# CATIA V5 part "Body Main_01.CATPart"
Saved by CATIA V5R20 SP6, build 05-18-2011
Part number: Body Main_01
Bounding box of the stored display mesh (mm): x -1450 to 0, y -340 to 340, z 0 to 599.993
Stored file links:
  E:\#03 University\#02 영남 이공대\#01 2021\#02 여름 방학\#01 Documents\K-Move Page02 ASD01\Body Main_01.CATPart
  E:\#03 University\#02 영남 이공대\#01 2021\#02 여름 방학\#01 Documents\K-Move Page02 ASD01\Body Main_04.CATPart

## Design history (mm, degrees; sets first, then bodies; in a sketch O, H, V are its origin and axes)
Set1 "Reference Data"
  Point1 "Center Point": (0, 0, 0)
  Plane1 "Plane.1(X Dir=-1150mm)": type Offset, RefPlane yz-plane, Offset -1150
  Plane2 "Plane.2(Z Dir=540mm)": type Offset, RefPlane xy-plane, Offset 540
  Extract1: ExtractElem face of Pad1 from Sketch1.L1
  Boundary1: Boundary edge of Extract1
Body1 (main body)
  Body2
    Sketch1 on zx-plane, origin (0, 0, 0), H (-1, 0, 0), V (0, 0, 1)
      line L1 (0, 0) -> (0, 540)
      line L2 (0, 540) -> (1003.9895, 540)
      point P2 (1150, 540)
      arc A1 centre (814, 0) radius 636 from (1326.0055, 377.2881) to (1450, 0) cw
      point P4 (1450, 0)
      construction line L3 (1450, 0) -> (1450, -100.3017)
      arc A2 centre (1003.9895, 140) radius 400 from (1003.9895, 540) to (1326.0055, 377.2881) cw
      line L4 (0, 0) -> (1450, 0)
      reference intersected line E1 through (1150, 0) direction (0, -1) from Plane1
      distance H L2 = 540
      distance V P4 = 1450
      radius A2 = 400
      vertical: L1 V, L3 V
      horizontal: L2 H, L4 H
      coincidence: P4 H, L2 P2, A1 P2, P2 E1
      tangency: L3 A1, A2 L2, A2 A1
    Pad1: profile Sketch1, direction (0, 1, 0), length 340, mirrored extent
    Fillet1: radius 20, on edge [face of Pad1 from Sketch1.L2 | end face of Pad1]; edge [start face of Pad1 | face of Pad1 from Sketch1.L2]
  Assemble1: tool Body2
  Body3
    Sketch2 on zx-plane, origin (0, 0, 0), H (-1, 0, 0), V (0, 0, 1)
      line L1 (1150, 0) -> (1150, 540)
      point P2 (1150, 540)
      arc A1 centre (1050, 540) radius 100 from (1150, 540) to (1136.6025, 590) ccw
      arc A2 centre (876.7949, 1040) radius 500 from (1109.9556, 597.6923) to (876.7949, 540) cw
      point P5 (876.7949, 540)
      line L2 (876.7949, 540) -> (876.7949, 0)
      line L3 (876.7949, 0) -> (1150, 0)
      reference intersected line E1 through (1150, 0) direction (0, -1) from Plane1
      arc A3 centre (1119.282, 580) radius 20 from (1136.6025, 590) to (1109.9556, 597.6923) ccw
      reference intersected line E2 through (0, 540) direction (-1, 0) from Plane2
      reference intersected line E3 through (0, 540) direction (-1, 0) from Plane2
      reference intersected line E4 through (0, 540) direction (-1, 0) from Plane2
      reference intersected line E5 through (0, 540) direction (-1, 0) from Plane2
      radius A2 = 500
      radius A1 = 100
      radius A3 = 20
      distance A3 E2 = 60
      vertical: L1 V, L2 V
      tangency: A1 L1, A3 A1, A3 A2, A2 E4
      horizontal: L3 H
      coincidence: L1 E1, P2 E3, P5 E5, L3 H
    Pad2: profile Sketch2, direction (0, 1, 0), length 330, mirrored extent
    Draft1: Angle 10, Neutral Plane2, PullDir Plane2, SupportToDraft (end face of Pad2; start face of Pad2)
    Fillet2: radius 20, on edge [end face of Pad2 | face of Pad2 from Sketch2.A2]; edge [start face of Pad2 | face of Pad2 from Sketch2.A2]; edge [face of Pad2 from Sketch2.L1 | end face of Pad2]; edge [start face of Pad2 | face of Pad2 from Sketch2.L1]
  Assemble2: tool Body3
  Shell1: ExtOffset 0, Face face of Pad1 from Sketch1.L1, IntOffset 5
  Body4
    Solid1: linked copy from another document
  Remove1: tool Body4
  Body5 "Hole Body"
    Sketch3 on zx-plane, origin (0, 0, 0), H (-1, 0, 0), V (0, 0, 1)
      circle A1 centre (990, 40) radius 20
      point P1 (990, 40)
      distance V P1 = 990
      distance H P1 = 40
      radius A1 = 20
    Sketch4 on zx-plane, origin (0, 0, 0), H (-1, 0, 0), V (0, 0, 1)
      circle A1 centre (50, 40) radius 20
      point P1 (50, 40)
      distance V P1 = 50
      distance H P1 = 40
      radius A1 = 20
    Pad3: profile Sketch3, direction (0, 1, 0), length 500, mirrored extent
    Pad4: profile Sketch4, direction (0, 1, 0), length 500, mirrored extent
  Remove2: tool Body5
  Body6 "Upper Pocket Body"
    Sketch5 on xy-plane, origin (0, 0, 0), H (-1, 0, 0), V (0, -1, 0)
      point P1 (0, 250)
      line L1 (0, 250) -> (1100, 250)
      line L2 (1100, 250) -> (1100, -250)
      line L3 (1100, -250) -> (0, -250)
      line L4 (0, -250) -> (0, 250)
      distance L4 L2 = 1100
      distance L1 L3 = 500
      coincidence: P1 V
      horizontal: L1 H, L3 H
      vertical: L2 V, L4 V
      symmetry: L1 L3 H
    Pad5: profile Sketch5, direction (0, 0, 1), length 800, opposite side length -400
  Remove3: tool Body6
